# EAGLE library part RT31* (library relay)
Power PCB Relayl SCHRACK 1 pole 12 / 16 A, DC- or AC-coi Source: http://www.schrack.com/.. 5819.pdf
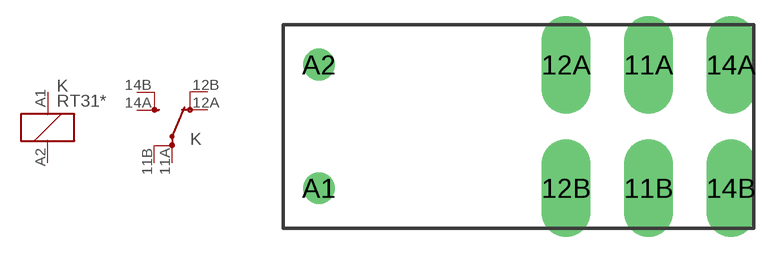
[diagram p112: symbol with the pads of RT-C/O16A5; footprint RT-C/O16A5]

Designator prefix K; gates 1=K 2=U-X2

## RT314005 (MPN: RT314005; OC_FARNELL: 1629043; OC_NEWARK: 03P2418), RT314006 (OC_FARNELL: unknown; OC_NEWARK: unknown), RT314012 (MPN: RT314012; OC_FARNELL: 1629044; OC_NEWARK: 03P2419), RT314024 (MF: TYCO ELECTRONICS; MPN: RT314024; OC_FARNELL: 1629045; OC_NEWARK: 36K2037), RT314048 (MPN: RT314048; OC_FARNELL: 1629046; OC_NEWARK: 03P2421), RT314060 (MPN: RT314060; OC_FARNELL: unknown; OC_NEWARK: 16R6367), RT314110 (MPN: RT314110; OC_FARNELL: unknown; OC_NEWARK: 48M7956), RT314524 (MPN: RT314524; OC_FARNELL: 1629047; OC_NEWARK: 03P2422), RT314615 (MF: TYCO ELECTRONICS; MPN: RT314615; OC_FARNELL: 1629048; OC_NEWARK: 08H3745), RT314730 (MPN: RT314730; OC_FARNELL: 1629051; OC_NEWARK: 03P2424)  [RT-C/O16A5]
11A  2:PA  pas
11B  2:PB  pas
12A  2:OA  pas
12B  2:OB  pas
14A  2:SA  pas
14B  2:SB  pas
A1  1:1  pas
A2  1:2  pas

## Footprint RT-C/O16A5 (pad centres in mm)
Power PCB Relay 1 pole 12 / 16 A, DC- or AC-coil SCHRACK 16 A, pinning 5mm Source: http://www.schrack.com/.. 5819.pdf
drill 1.3 pad 3 long: 11A 7.56,3.78; 11B 7.56,-3.78; 12A 2.52,3.78; 12B 2.52,-3.78; 14A 12.6,3.78; 14B 12.6,-3.78
drill 1.3 round: A1 -12.6,-3.78; A2 -12.6,3.78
